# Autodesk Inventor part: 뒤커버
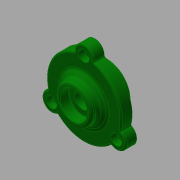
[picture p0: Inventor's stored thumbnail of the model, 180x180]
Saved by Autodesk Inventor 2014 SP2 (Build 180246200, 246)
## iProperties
Created: 2016-05
Part Number: 뒤커버
Document SubType Name: Modeling
Designer: mduedu
Density: 2.71 g/cm^3
Material: 알루미늄 6061
Appearance: 진녹색
Author: mduedu
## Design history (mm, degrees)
sketch "스케치1"
  geometry: C1 r 17.5 at (0, 0); C2 r 27.5 at (0, 0); 1 further point
  constraints: 2 centre point, 2 coincident
  dimensions: "d33" = 55 diameter of C2; "d34" = 35 diameter of C1
extrude "돌출1" new body sketch "스케치1" distance "d0" = 8; taper "d1" = 0 deg
extrude "돌출2" join sketch "스케치1" distance "d2" = 8; taper "d3" = 0 deg; dims "d35" = 9, "d36" = 0
sketch "스케치5"
  geometry: L1 (-27.5, 8)-(27.5, 8) reference; L2 (0, 0)-(0, 15); L3 (-27.5, 0)-(27.5, 0) reference; L4 (17.5, 8)-(0, 8); A1 r 25.375 centre (0, -10.375) between (17.5, 8) and (0, 15)
  constraints: 4 end point, 3 point on line, 2 point on circle, 1 centre point, 1 midpoint, 1 perpendicular
  dimensions: "d37" = 17.5 distance from line of L2 L4.start; "d39" = 7 distance from line of L1 L2.end
revolve "회전2" sketch "스케치5" stored, may be unused: angle "d40" = 90 deg
node "작업 평면1"
sketch "스케치6"
  geometry: C1 r 13.5 at (0, 0); 1 further point
  constraints: 1 centre point, 1 coincident
  dimensions: "d42" = 27 diameter of C1
extrude "돌출4" join sketch "스케치6" stored distance "d43" = 10; taper "d44" = 0 deg
sketch "스케치4"
  geometry: L1 (0, -9)-(0, 16); L2 (-15, -9)-(-15, 0); L3 (-15, 0)-(-10, 0); L4 (-10, 0)-(-10, 3); L5 (-10, 3)-(-6, 3); L6 (-6, 3)-(-6, 9); L7 (-6, 9)-(-10, 9); L8 (-10, 9)-(-10, 16); L9 (17.5, -9)-(-17.5, -9) reference; L10 (-13.5, 16)-(13.5, 16) reference; 1 further point
  constraints: 16 end point, 6 parallel, 3 point on line, 2 midpoint, 1 perpendicular, 1 vertical
  dimensions: "d15" = 30 diameter of L2 L1; "d16" = 20 diameter of L8 L1; "d18" = 9 distance of L2.start L2.end; "d19" = 3 distance of L3.end L4.end; "d20" = 20 diameter of L4 L1; "d21" = 12 diameter of L6 L1; "d45" = 7 distance of L7.end L8.end
revolve "회전1" sketch "스케치4" stored, may be unused: angle "d22" = 90 deg
fillet "모깎기2" dims "d23" = 3
fillet "모깎기3" dims "d24" = 0.3
chamfer "모따기2" distance "d46" = 0.5; stored, may be unused: second distance "d47" = 2, angle "d48" = 45 deg
fillet "모깎기4" dims "d49" = 3
fillet "모깎기5" dims "d50" = 2
sketch "스케치7"
  geometry: C1 r 7 at (0, 27.5); 2 further points
  constraints: 3 vertical alignment, 1 centre point, 2 other
  dimensions: "d54" = 14 diameter of C1
extrude "돌출5" join sketch "스케치7" stored distance "d55" = 10; taper "d56" = 0 deg
fillet "모깎기6" dims "d57" = 1
fillet "모깎기7" dims "d61" = 1
sketch "스케치8" dims "d62" = 55 (derived)
  geometry: C1 r 18.661 at (0, 0) reference; A1 r 2 centre (-7.999, 27.355) between (-7.437, 25.435) and (-5.999, 27.391) reference; A2 r 26.5 centre (0, 0) between (-7.437, 25.435) and (-25.746, -6.277) reference; A3 r 2 centre (-27.689, -6.75) between (-26.721, -8.5) and (-25.746, -6.277) reference; A4 r 6 centre (-23.816, -13.75) between (-26.721, -8.5) and (-20.722, -18.891) reference; A5 r 2 centre (-19.69, -20.604) between (-18.309, -19.158) and (-20.722, -18.891) reference; A6 r 26.5 centre (0, 0) between (-18.309, -19.158) and (18.309, -19.158) reference; A7 r 2 centre (19.69, -20.604) between (20.722, -18.891) and (18.309, -19.158) reference; A8 r 6 centre (23.816, -13.75) between (20.722, -18.891) and (26.721, -8.5) reference; A9 r 2 centre (27.689, -6.75) between (25.746, -6.277) and (26.721, -8.5) reference; A10 r 26.5 centre (0, 0) between (25.746, -6.277) and (7.437, 25.435) reference; A11 r 2 centre (7.999, 27.355) between (5.999, 27.391) and (7.437, 25.435) reference; A12 r 6 centre (0, 27.5) between (5.999, 27.391) and (-5.999, 27.391) reference; 4 further points
  constraints: 2 coincident, 1 vertical alignment, 6 other
  dimensions: "d65" = 360 deg dimension on A2.centre point (0, 27.5) (derived)
sketch "스케치9"
  geometry: 3 further points
  constraints: 3 other
hole "구멍2" sketch "스케치9" at (-23.816, -13.75), (23.816, -13.75), (0, 27.5) diameter "d67" = 4.5; stored, may be unused: countersink angle "d71" = 90 deg, drill point angle "d73" = 0 deg; dims "d68" = 6, "d69" = 8, "d70" = 4.6, "d72" = 8
node "솔리드1"
pattern_circular "원형 패턴1" dims angle "d59" = 360 deg
other parameters: "d41" = 8
